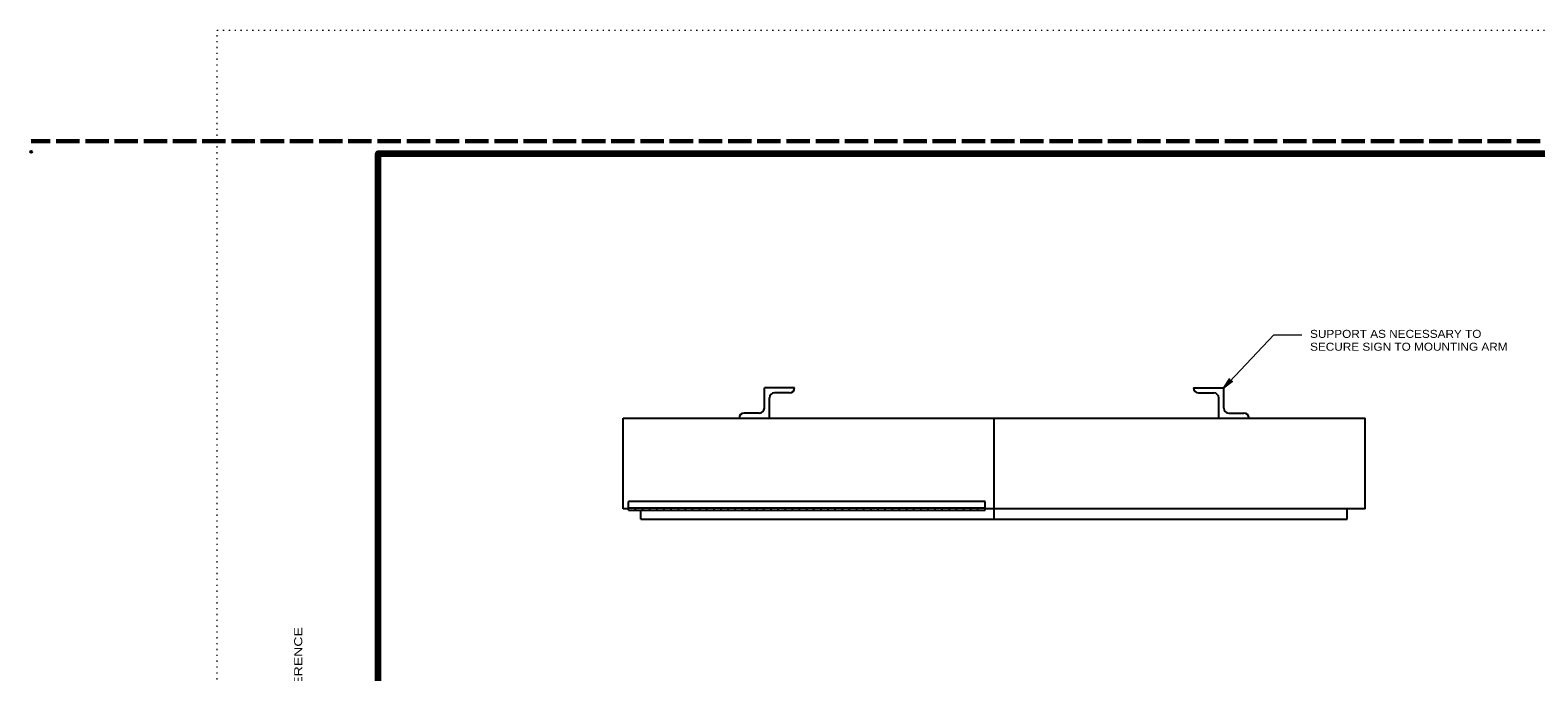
# Model space of a CAD drawing. Extents: x 312583 to 312854, y 144419 to 144597.
# Drawn here: x 312583.4 to 312726.5, y 144535.8 to 144596.8 of the extents above; entities that cross this region are included whole.
import ezdxf

# ---------------------------------------------------------------- set-up
doc = ezdxf.new("R2010")
doc.units = 0
doc.header["$LTSCALE"] = 0.37
doc.header["$PDMODE"] = 32
doc.header["$PDSIZE"] = 0.185
doc.linetypes.add('DOTTED', pattern=[1.5, 0.3, -1.2])
doc.linetypes.add('LONG_DASHED', pattern=[7.5, 6, -1.5])
for name, color, linetype, lineweight in [('1', 7, 'Continuous', 25), ('2', 7, 'Continuous', 25), ('62', 7, 'DOTTED', 13), ('63', 7, 'LONG_DASHED', 60)]:
    doc.layers.add(name, color=color, linetype=linetype, lineweight=lineweight)

msp = doc.modelspace()

# ---------------------------------------------------------------- linework, layer by layer
at = {"layer": '1'}
for p, q in [((312653.1801, 144560.8992), (312653.1801, 144562.8159)), ((312656.0551, 144562.8159), (312653.1801, 144562.8159)), ((312693.9438, 144562.8159), (312696.8188, 144562.8159)), ((312696.8188, 144560.8992), (312696.8188, 144562.8159)), ((312653.6555, 144559.9409), (312653.6555, 144561.8576)), ((312655.5721, 144562.3329), (312654.1385, 144562.3329)), ((312694.4191, 144562.3329), (312695.8605, 144562.3329)), ((312696.3358, 144559.9409), (312696.3358, 144561.8576)), ((312639.7635, 144559.9409), (312710.2355, 144559.9409)), ((312639.7635, 144551.3159), (312639.7635, 144559.9409)), ((312652.6971, 144560.4162), (312651.2635, 144560.4162)), ((312674.9995, 144550.3576), (312674.9995, 144559.9409)), ((312697.2941, 144560.4162), (312698.7355, 144560.4162)), ((312710.2355, 144551.3159), (312710.2355, 144559.9409)), ((312640.2695, 144551.3159), (312639.7635, 144551.3159)), ((312640.2695, 144551.1932), (312640.2695, 144552.0366)), ((312674.1485, 144552.0366), (312640.2695, 144552.0366)), ((312640.2695, 144551.4309), (312674.1485, 144551.4309)), ((312640.2695, 144551.1932), (312674.1485, 144551.1932)), ((312640.9441, 144551.1932), (312640.9441, 144551.4309)), ((312641.4578, 144550.3576), (312641.4578, 144551.1932)), ((312641.6265, 144551.1932), (312641.6265, 144551.4309)), ((312642.3011, 144551.1932), (312642.3011, 144551.4309)), ((312642.9758, 144551.1932), (312642.9758, 144551.4309)), ((312643.6581, 144551.1932), (312643.6581, 144551.4309)), ((312644.3328, 144551.1932), (312644.3328, 144551.4309)), ((312645.0151, 144551.1932), (312645.0151, 144551.4309)), ((312645.6898, 144551.1932), (312645.6898, 144551.4309)), ((312646.3645, 144551.1932), (312646.3645, 144551.4309)), ((312647.0468, 144551.1932), (312647.0468, 144551.4309)), ((312647.7215, 144551.1932), (312647.7215, 144551.4309)), ((312648.3961, 144551.1932), (312648.3961, 144551.4309)), ((312649.0785, 144551.1932), (312649.0785, 144551.4309)), ((312649.7531, 144551.1932), (312649.7531, 144551.4309)), ((312650.4355, 144551.1932), (312650.4355, 144551.4309)), ((312651.1101, 144551.1932), (312651.1101, 144551.4309)), ((312651.7848, 144551.1932), (312651.7848, 144551.4309)), ((312652.4671, 144551.1932), (312652.4671, 144551.4309)), ((312653.1418, 144551.1932), (312653.1418, 144551.4309)), ((312653.8165, 144551.1932), (312653.8165, 144551.4309)), ((312654.4988, 144551.1932), (312654.4988, 144551.4309)), ((312655.1735, 144551.1932), (312655.1735, 144551.4309)), ((312655.8558, 144551.1932), (312655.8558, 144551.4309)), ((312656.5305, 144551.1932), (312656.5305, 144551.4309)), ((312657.2051, 144551.1932), (312657.2051, 144551.4309)), ((312657.8875, 144551.1932), (312657.8875, 144551.4309)), ((312658.5621, 144551.1932), (312658.5621, 144551.4309)), ((312659.2368, 144551.1932), (312659.2368, 144551.4309)), ((312659.9191, 144551.1932), (312659.9191, 144551.4309)), ((312660.5938, 144551.1932), (312660.5938, 144551.4309)), ((312661.2761, 144551.1932), (312661.2761, 144551.4309)), ((312661.9508, 144551.1932), (312661.9508, 144551.4309)), ((312662.6255, 144551.1932), (312662.6255, 144551.4309)), ((312663.3078, 144551.1932), (312663.3078, 144551.4309)), ((312663.9825, 144551.1932), (312663.9825, 144551.4309)), ((312664.6571, 144551.1932), (312664.6571, 144551.4309)), ((312665.3395, 144551.1932), (312665.3395, 144551.4309)), ((312666.0141, 144551.1932), (312666.0141, 144551.4309)), ((312666.6965, 144551.1932), (312666.6965, 144551.4309)), ((312667.3711, 144551.1932), (312667.3711, 144551.4309)), ((312668.0458, 144551.1932), (312668.0458, 144551.4309)), ((312668.7281, 144551.1932), (312668.7281, 144551.4309)), ((312669.4028, 144551.1932), (312669.4028, 144551.4309)), ((312670.0775, 144551.1932), (312670.0775, 144551.4309)), ((312670.7598, 144551.1932), (312670.7598, 144551.4309)), ((312671.4345, 144551.1932), (312671.4345, 144551.4309)), ((312672.1168, 144551.1932), (312672.1168, 144551.4309)), ((312672.7915, 144551.1932), (312672.7915, 144551.4309)), ((312673.4661, 144551.1932), (312673.4661, 144551.4309)), ((312674.1485, 144551.1932), (312674.1485, 144552.0366)), ((312710.2355, 144551.3159), (312674.1485, 144551.3159)), ((312708.5411, 144550.3576), (312708.5411, 144551.3159)), ((312641.4578, 144550.3576), (312708.5411, 144550.3576))]:
    msp.add_line(p, q, dxfattribs=at)
at = {"layer": '1', "lineweight": 158}
msp.add_lwpolyline([(312616.5, 144423.1446), (312616.5, 144585.0846), (312849, 144585.0846)], dxfattribs=at)
at = {"layer": '1'}
for centre, start, end in [((312655.575, 144562.814), 270, 0), ((312694.422, 144562.814), 180, 270), ((312654.1375, 144561.8556), 90, 180), ((312695.8595, 144561.8556), 0, 90), ((312651.2625, 144559.939), 90, 180), ((312652.7, 144560.8973), 270, 0), ((312697.297, 144560.8973), 180, 270), ((312698.7345, 144559.939), 0, 90)]:
    msp.add_arc(centre, 0.4792, start, end, dxfattribs=at)
msp.add_point((312583.526, 144585.2246), dxfattribs=at)
at = {"layer": '2', "lineweight": 13}
for p, q in [((312696.8188, 144562.8159), (312701.5721, 144567.8529)), ((312701.5721, 144567.8529), (312704.2171, 144567.8529))]:
    msp.add_line(p, q, dxfattribs=at)
at = {"layer": '2'}
msp.add_lwpolyline([(312696.8188, 144562.8159), (312697.6008, 144563.4062), (312697.2635, 144563.2836), (312697.3631, 144563.6286)], close=True, dxfattribs=at)
at = {"layer": '62'}
for p, q in [((312601.2, 144596.7846), (312853.5, 144596.7846)), ((312601.2, 144418.5846), (312601.2, 144596.7846))]:
    msp.add_line(p, q, dxfattribs=at)
at = {"layer": '63'}
msp.add_line((312851.75, 144586.2246), (312583.526, 144586.2246), dxfattribs=at)

# ---------------------------------------------------------------- texts
at = {"layer": '1', "width": 1.3}
msp.add_text('REFERENCE                                                              ', height=0.7682, rotation=90, dxfattribs=at).set_placement((312609.2854, 144531.8549))
at = {"layer": '2', "width": 1.1}
for s, p in [('SUPPORT AS NECESSARY TO', (312705.0145, 144567.5606)), ('SECURE SIGN TO MOUNTING ARM', (312705.0145, 144566.3406))]:
    msp.add_text(s, height=0.76, dxfattribs=at).set_placement(p)

doc.saveas('drawing.dxf')
